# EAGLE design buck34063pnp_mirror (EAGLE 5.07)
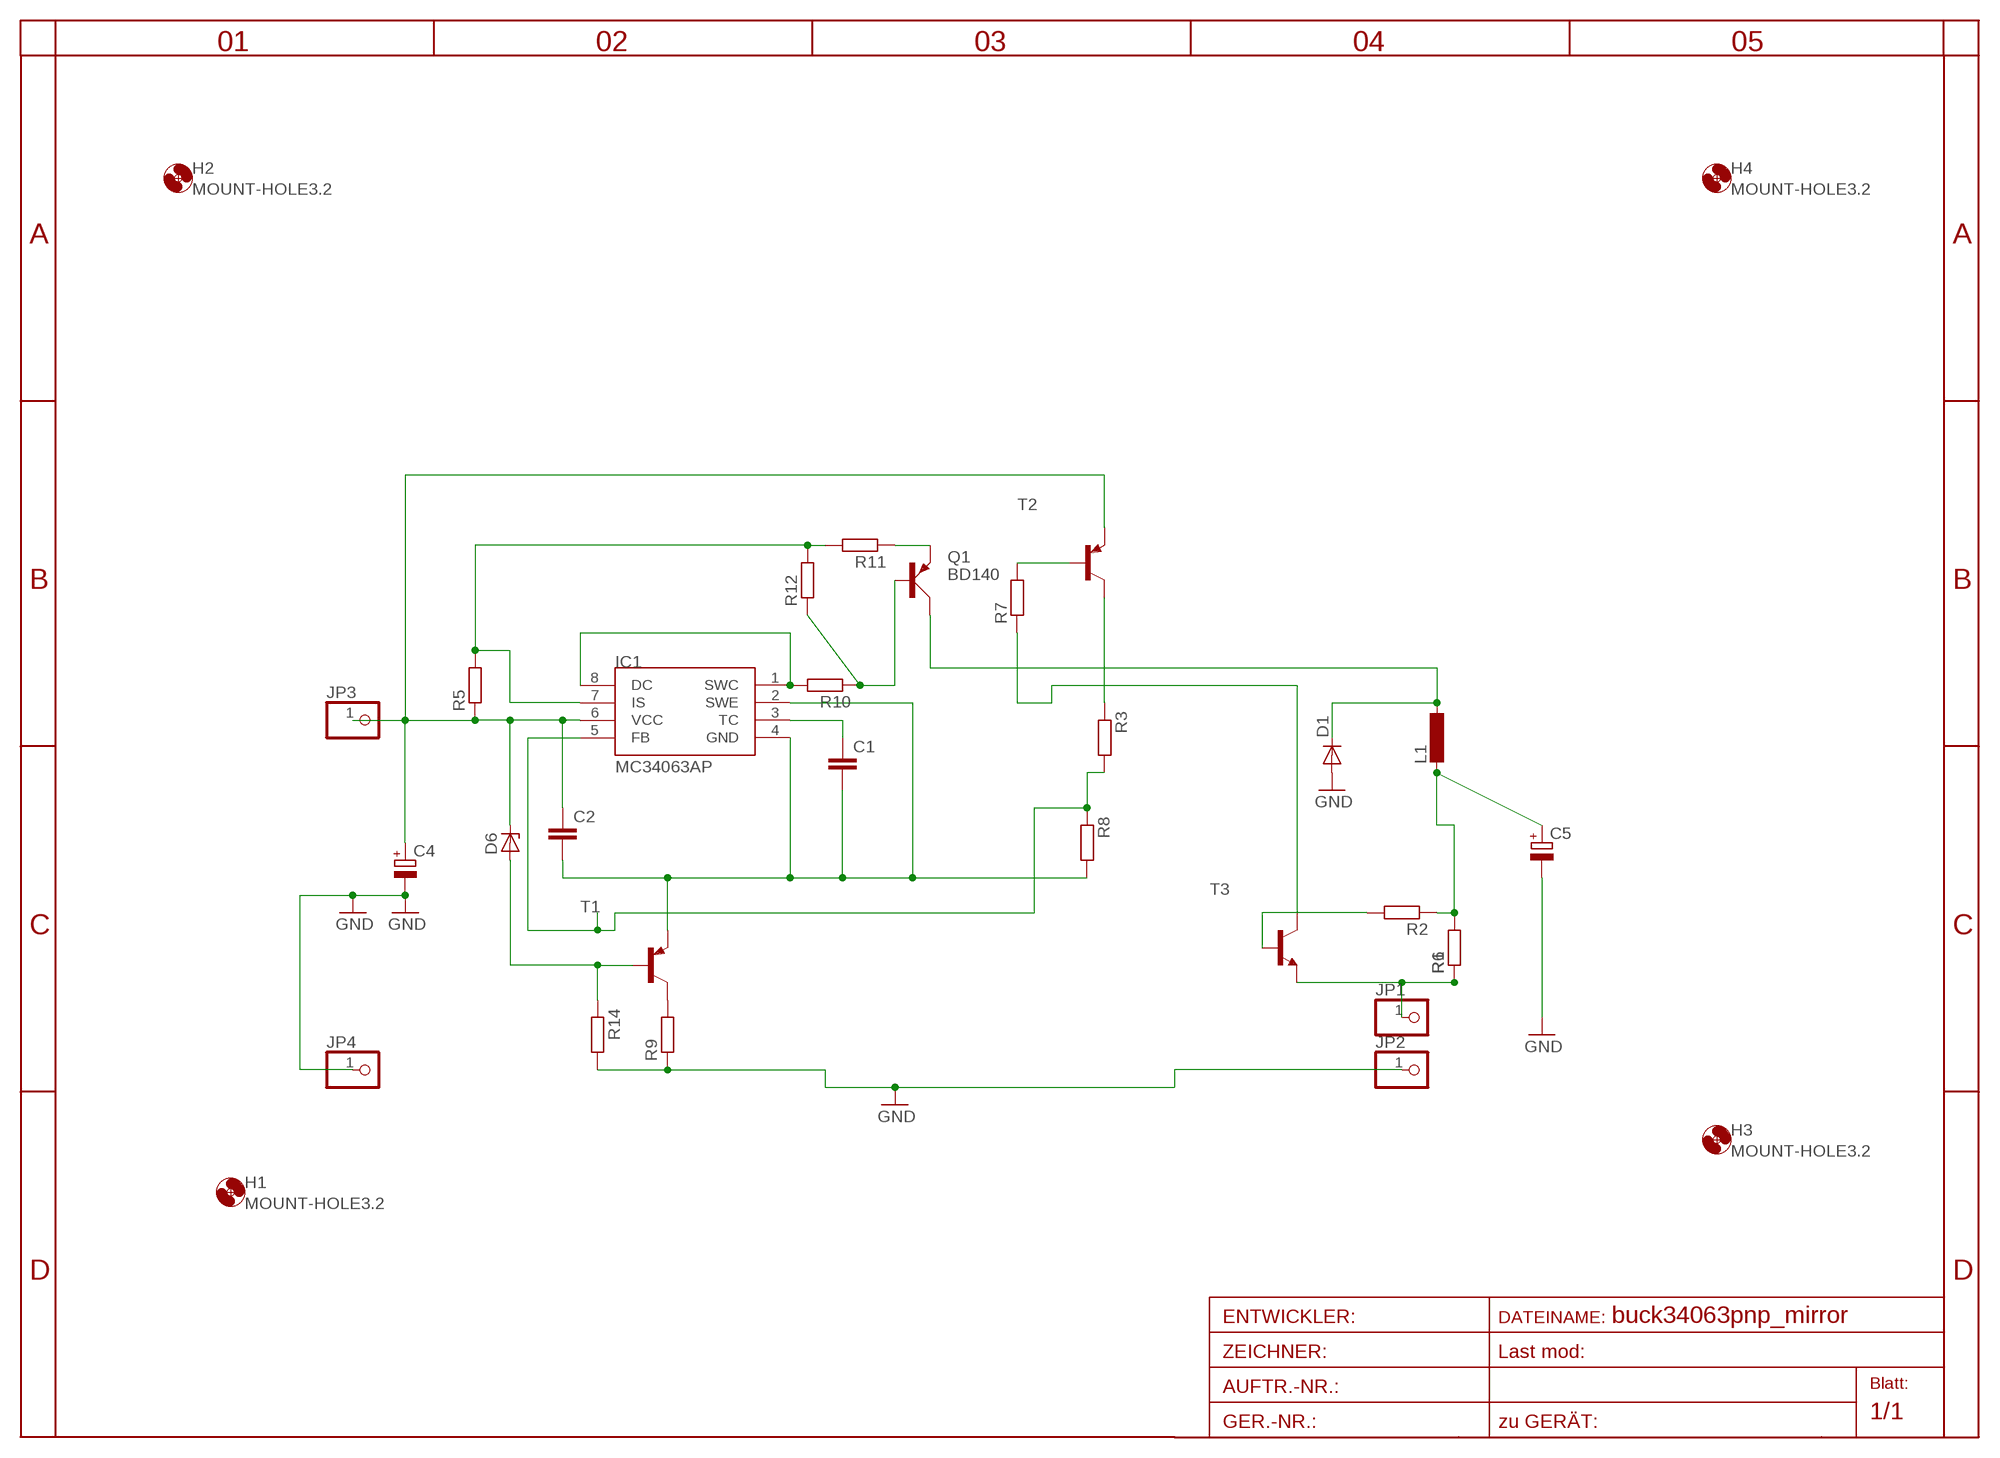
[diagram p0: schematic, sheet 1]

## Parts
C1  C-EUC1206  [C1206]
C2  C-EUC1206  [C1206]
C4  CPOL-EUE5-10.5  [E5-10,5]
C5  CPOL-EUE5-10.5  [E5-10,5]
D1  DIODE-SMC  [SMC]
D6  ZENER-DIODEZD-7.5  [ZDIO-7.5]
H1  MOUNT-HOLE3.2  [3,2]
H2  MOUNT-HOLE3.2  [3,2]
H3  MOUNT-HOLE3.2  [3,2]
H4  MOUNT-HOLE3.2  [3,2]
IC1  MC34063AP  [DIL08]
JP1  PINHD-1X11MM6  [1X1MM8]
JP2  PINHD-1X11MM6  [1X1MM8]
JP3  PINHD-1X11MM6  [1X1MM8]
JP4  PINHD-1X11MM6  [1X1MM8]
L1  L-EU0207/10  [0207/10]
Q1  BD140  [TO126AV]
R1  R-EU_0207/10  [0207/10]
R2  R-EU_0204/7  [0204/7]
R3  R-EU_0204/7  [0204/7]
R5  R-EU_0207/10  [0207/10]
R6  R-EU_R2010  [R2010]
R7  R-EU_0207/35  [0207/35]
R8  R-EU_0207/10  [0207/10]
R9  R-EU_0207/12  [0207/12]
R10  R-EU_0204/7  [0204/7]
R11  R-EU_0411/15  [0411/15]
R12  R-EU_0207/7  [0207/7]
R14  R-EU_0207/12  [0207/12]
T1  BC857A-PNP-SOT23-BEC  [SOT23-BEC]
T2  BC857A-PNP-SOT23-BEC  [SOT23-BEC]
T3  BC847ALT1-NPN-SOT23-BEC  [SOT23-BEC]

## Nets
B-LO: R2.2 T3.B
B-M2: R7.2 T2.B
B-PNP: Q1.B R10.1 R12.1
C-HI: R9.2 T1.C
C-LO: R7.1 T3.C
C-M2: R3.1 T2.C
C-PNP: D1.C L1.1 Q1.C
DC: IC1.1(SWC) IC1.8(DC) R10.2
E: IC1.7(IS) R5.2 R11.2 R12.2
E-HI: D6.A R14.1 T1.B
E-PNP: Q1.E R11.1
FB: IC1.5(FB) R3.2 R8.1
GND: C4.- C5.- D1.A JP2.1 JP4.1 R9.1 R14.2
TC: C1.1 IC1.3(TC)
VCC: C2.1 C4.+ D6.C IC1.6(VCC) JP3.1 R5.1 T2.E
VOUT: JP1.1 R1.1 R6.1 T3.E
VOUT-P: C5.+ L1.2 R1.2 R2.1 R6.2
VRTGND: C1.2 C2.2 IC1.2(SWE) IC1.4(GND) R8.2 T1.E

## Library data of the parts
C1 C2 = rcl:C-EU: CAPACITOR, European symbol
C4 C5 = rcl:CPOL-EU: POLARIZED CAPACITOR, European symbol
D1 = diode:DIODE-: DIODE
D6 = diode:ZENER-DIODE: Z-Diode
H1-H4 = holes:MOUNT-HOLE: MOUNTING HOLE with drill center marker
IC1 = mc34063:MC34063
JP1-JP4 = pinhead:PINHD-1X1: PIN HEADER
L1 = rcl:L-EU: INDUCTOR, European symbol
Q1 = transistor-power:BD140: PNP TRANSISTOR
R1-R3 R5 R6 R8-R12 R14 = rcl:R-EU_: RESISTOR, European symbol
R7 = rcl-2:R-EU_: RESISTOR, European symbol
T1 T2 = transistor:*-PNP-: PNP Transistror
T3 = transistor:*-NPN-: NPN Transistror BF959 corrected 2008.03.06

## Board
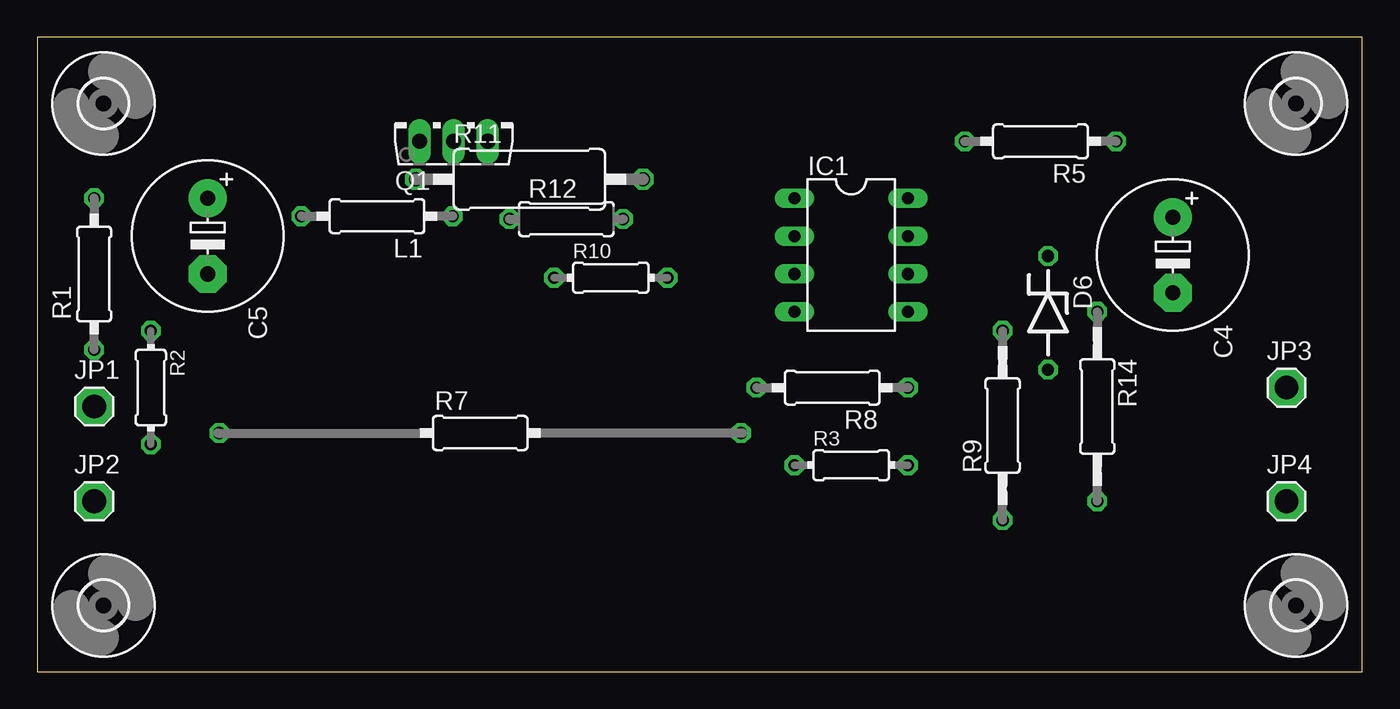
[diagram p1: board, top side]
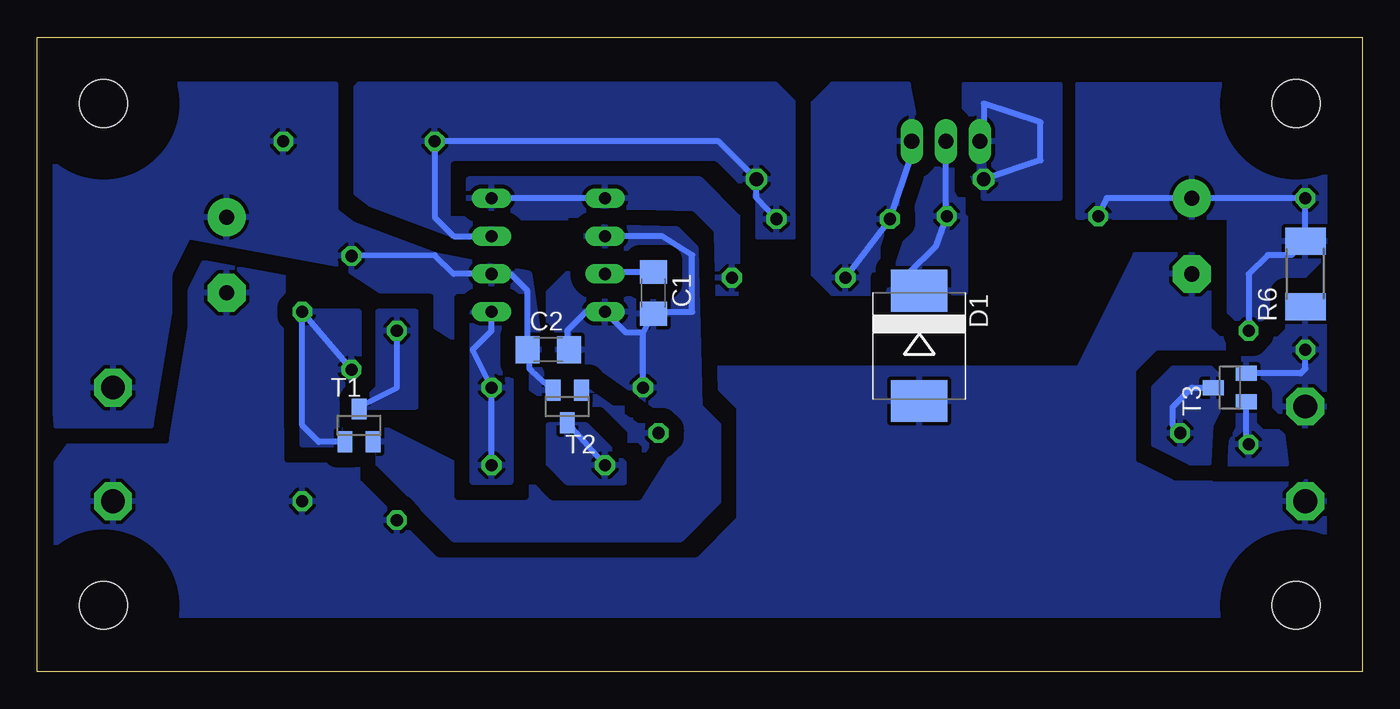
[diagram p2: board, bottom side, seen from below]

Size 88.9 x 42.55 mm. Coordinates in mm from the lower left corner, seen from the top.
Outline: 0,0 88.9,0 88.9,42.55 0,42.55 0,0
Copper layers (1*16): Top 0.035mm / dielectric 1.5mm / Bottom 0.035mm
Design rules "default": minimum track width 10mil, minimum drill 24mil, track to track 8mil, track to pad 8mil, pad to pad 8mil, via to via 8mil, smd to smd 8mil, copper to edge 40mil, drill to drill 8mil, minimum pad ring 10mil, minimum via ring 8mil, stop-mask expansion 4mil, vias tented up to drill 0mil, thermal gap 10mil

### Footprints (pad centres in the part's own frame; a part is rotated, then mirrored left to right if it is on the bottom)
C1206 = smd 1.6 x 1.8: 1 -1.4,0; 2 1.4,0
E5-10,5 = drill 1.016 pad 2.54 round: + -2.54,0 | drill 1.016 pad 2.54 octagon: - 2.54,0
SMC = smd 2.8 x 3.8: A 3.7,0; C -3.7,0
ZDIO-7.5 = drill 0.813 octagon: A 3.81,0; C -3.81,0
3,2 = hole 3.2: 0,0
DIL08 = drill 0.813 long: 1 -3.81,-3.81; 2 -1.27,-3.81; 3 1.27,-3.81; 4 3.81,-3.81; 5 3.81,3.81; 6 1.27,3.81; 7 -1.27,3.81; 8 -3.81,3.81
1X1MM8 = drill 1.6 pad 2.54 octagon: 1 0,0
0207/10 = drill 0.813 octagon: 1 -5.08,0; 2 5.08,0
TO126AV = drill 1.016 long: B 2.286,-1.27; C 0,-1.27; E -2.286,-1.27
0204/7 = drill 0.813 octagon: 1 -3.81,0; 2 3.81,0
R2010 = smd 1.8 x 2.7: 1 -2.2,0; 2 2.2,0
0207/35 = drill 0.813 octagon: 1 -17.5,0; 2 17.5,0
0207/12 = drill 0.813 octagon: 1 -6.35,0; 2 6.35,0
0411/15 = drill 0.914 octagon: 1 -7.62,0; 2 7.62,0
0207/7 = drill 0.813 octagon: 1 -3.81,0; 2 3.81,0
SOT23-BEC = smd 1 x 1.4: B -0.95,-1.1; C 0,1.1; E 0.95,-1.1

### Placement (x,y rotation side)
C1  47.56,25.4 270 bottom
C2  54.61,21.59 0 bottom
C4  76.2,27.94 270 top
C5  11.43,29.21 270 top
D1  29.72,21.84 270 bottom
D6  67.82,24.07 270 top
H1  84.45,38.1 0 top
H2  84.45,4.45 0 top
H3  4.45,4.45 0 top
H4  4.45,38.1 0 top
IC1  54.61,27.94 270 top
JP1  3.81,17.78 0 top
JP2  3.81,11.43 0 top
JP3  83.82,19.05 0 top
JP4  83.82,11.43 0 top
L1  22.8,30.54 180 top
Q1  27.94,36.83 0 top
R1  3.81,26.67 90 top
R2  7.62,19.05 270 top
R3  54.61,13.84 0 top
R5  67.31,35.56 180 top
R6  3.81,26.67 90 bottom
R7  29.72,16 0 top
R8  53.34,19.05 180 top
R9  64.77,16.51 90 top
R10  38.48,26.42 0 top
R11  33.02,33.02 0 top
R12  35.5,30.35 0 top
R14  71.12,17.78 270 top
T1  67.31,16.51 0 bottom
T2  53.34,17.78 180 bottom
T3  8.89,19.05 90 bottom

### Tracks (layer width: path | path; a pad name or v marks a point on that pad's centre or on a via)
B-LO
  Bottom 0.406: T3.B 7.79,15.41 R2.2
  pour Bottom (isolate 1.016, rank 4): 5.46,16.83 6.41,17.78 8.89,17.78 10.16,16.51 10.16,13.97 5.08,13.97
B-M2
  pour Bottom (isolate 1.016, rank 3): 50.8,19.05 53.34,19.05 53.34,17.78 49.53,13.97 46.99,13.97 45.72,15.24 45.72,16.51 46.99,17.78 48.26,17.78
B-PNP
  Bottom 0.406: Q1.B 30.23,34.67 R12.1 R10.1
  pour Bottom (isolate 1.016, rank 3): 30.48,39.37 35.56,39.37 36.83,38.1 36.83,26.67 35.56,25.4 33.02,25.4 29.21,33.02
C-HI
  Bottom 0.406: T1.C 67.31,17.78 64.77,19.05 R9.2
  pour Bottom: 63.5,24.13 66.04,24.13 66.04,19.05 67.31,17.78 63.5,17.78 63.5,20.32
C-LO
  Bottom 0.406: T3.C 11.43,19.05 12.7,17.78 12.7,16.48 R7.1
  pour Bottom (isolate 1.016, rank 3): 8.89,19.05 10.16,20.32 12.7,20.32 13.97,19.05 13.97,15.24 11.56,14.03 10.29,14.03 10.16,16.51
C-M2
  Bottom 0.406: R3.1 T2.C
  pour Bottom (isolate 1.016): 53.34,16.51 54.61,16.51 54.61,13.97 53.34,12.7 49.53,12.7 49.53,13.97 52.07,16.51
C-PNP
  Bottom 0.406: Q1.C 27.94,31.11 L1.1 28.57,28.57 30.48,26.67 30.48,26.31 D1.C
  pour Bottom (isolate 1.016, rank 2): 27.94,35.56 26.67,35.56 26.67,25.4 31.75,25.4 29.21,33.02 29.21,35.56
DC
  Bottom 0.406: IC1.1 IC1.8
  pour Bottom (isolate 1.016, rank 3): 44.45,25.4 41.91,25.4 41.91,30.48 44.45,33.02 59.94,33.02 59.94,30.48 46.99,30.48 44.45,27.94
E
  Bottom 0.406: R12.2 40.64,31.75 R11.2 43.18,35.56 R5.2 62.23,30.48 60.96,29.21 IC1.7
  pour Bottom (isolate 1.016, rank 4): 38.1,29.21 38.1,38.1 39.37,39.37 67.31,39.37 68.58,38.1 68.58,31.75 63.5,29.21 62.23,29.21 60.96,27.94 59.69,27.94 58.42,29.21 58.42,30.48 59.69,31.75 59.69,33.02 44.45,33.02 40.64,29.21
E-HI
  Bottom 0.406: D6.A R14.1 71.12,16.51 70.02,15.41 T1.B
  pour Bottom (isolate 0.813, rank 4): 67.31,20.32 67.31,24.13 71.12,24.13 71.12,15.24 68.58,15.24 68.58,19.05
E-PNP
  Bottom 0.406: R11.1 21.59,34.29 21.59,36.83 25.4,38.1 25.4,36.83 25.65,36.83 Q1.E
  pour Bottom (isolate 1.016): 26.67,34.29 26.67,39.37 20.32,39.37 20.32,31.75 25.4,31.75
FB
  Bottom 0.406: IC1.5 58.42,22.86 59.69,21.59 R8.1 R3.2
  pour Bottom (isolate 1.016): 57.15,12.7 59.69,12.7 59.69,24.13 57.15,24.13
GND
  pour Bottom (isolate 1.016, rank 5): 8.89,27.94 15.24,27.94 19.05,20.32 72.39,20.32 72.39,27.94 77.47,27.94 87.63,13.97 87.63,7.62 81.28,3.81 2.54,3.81 2.54,12.7 11.43,12.7 13.97,15.24 13.97,19.05 11.43,21.59 8.89,21.59
TC
  Bottom 0.406: C1.1 50.67,26.8 IC1.3
VCC
  Bottom 0.406: D6.C 62.23,27.94 60.96,26.67 IC1.6 57.15,26.67 56.01,25.53 C2.1 55.88,21.46 55.88,20.32 55.71,20.15 T2.E
  pour Bottom (isolate 1.016, rank 2): 80.01,39.37 88.9,33.02 87.63,16.51 81.28,16.51 80.01,24.13 80.01,26.67 78.74,29.21 68.58,27.3 54.61,18.22 55.88,26.67 62.23,27.94 67.69,29.97 68.9,30.86 68.9,39.37
VOUT
  Bottom 0.406: T3.E 4.13,20 3.81,20.32 R1.1
  pour Bottom (isolate 1.016, rank 2): 2.54,24.13 5.08,24.13 7.94,21.27 7.94,19.88 4.83,16.76 4.83,16.19 4.51,16.51 2.54,16.51
VOUT-P
  Bottom 0.406: R2.1 7.62,26.67 6.35,27.94 4.74,27.94 R6.2 R1.2 C5.+ 17.14,31.75 L1.2
  pour Bottom (isolate 1.016): 19.05,30.48 19.05,39.37 3.81,39.37 2.54,34.29 2.54,27.94 7.62,22.86 8.89,24.13 8.89,30.48
VRTGND
  Bottom 0.406: IC1.2 46.99,29.21 44.96,27.94 44.96,24.13 46.86,24.13 C1.2 48.26,22.73 | R8.2 48.26,22.73 | 48.26,22.73 49.4,22.73 IC1.4 52.07,24.13 53.34,22.86 53.34,21.72 C2.2
  pour Bottom (isolate 1.016, rank 2): 66.04,13.97 60.96,8.89 45.72,8.89 43.18,11.43 43.18,16.51 44.45,17.78 44.7,28.38 45.97,29.65 52.07,29.84 52.07,27.94 54.61,25.4 54.67,21.65 50.86,20.26 45.21,16.26 48.26,11.43 58.42,12.7 66.04,16.51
